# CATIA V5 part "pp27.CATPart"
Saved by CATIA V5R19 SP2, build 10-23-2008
Part number: pp27
Publications: "Line.1", "Point.2", "Plane.1", "Point.3", "Line.2", "Plane.2"
Bounding box of the stored display mesh (mm): x -20 to 0, y 0 to 100, z 0 to 50
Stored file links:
  C:\Users\Welcome\Documents\thinkm2\pp27.CATPart
  C:\Users\Welcome\Documents\thinkm2\Brasmeca.CATProduct
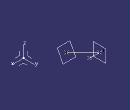
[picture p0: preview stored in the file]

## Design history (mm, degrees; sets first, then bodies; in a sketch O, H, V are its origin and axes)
AxisSystem1: origin (0, 0, 0), X (1, 0, 0), Y (0, 1, 0), Z (0, 0, 1)
Set1
  Point1: linked copy from another document
Body1 (main body)
  Line1: type PtDir, RefPoint Point1, Direction edge [XY plane of AxisSystem1 | ZX plane of AxisSystem1], Start 0, End -20
  Point2: type OnCurve, Support Line1, Length 5
  Plane1: type Normal, Curve Line1, RefPoint Point2
  Point3: (-15, 50, 25), in AxisSystem1
  Line2: type PtPt, FirstPoint Point2, SecondPoint Point3
  Plane2: type Normal, Curve Line2, RefPoint Point3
